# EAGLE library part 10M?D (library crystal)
Monolithic Crystal Filters Source: www.vanlong.com
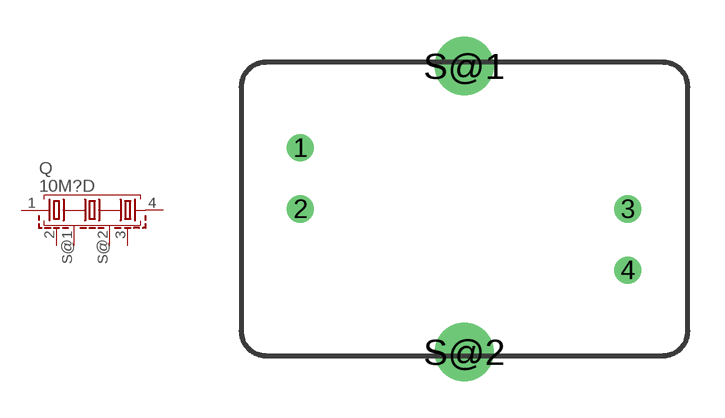
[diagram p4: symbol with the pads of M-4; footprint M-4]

Designator prefix Q

## 10M15D (OC_FARNELL: unknown; OC_NEWARK: unknown), 10M15D1 (OC_FARNELL: unknown; OC_NEWARK: unknown)  [M-4]
1  1  pas
2  2  pas
3  3  pas
4  4  pas
S@1  S  pas
S@2  S  pas

## Footprint M-4 (pad centres in mm)
Monolithic Crystal Filters Source: www.vanlong.com
drill 0.6 pad 1.016 round: 1 -6.7,2.5; 2 -6.7,0; 3 6.7,0; 4 6.7,-2.5
drill 1.6 pad 1.93 round: S@1 0,5.85; S@2 0,-5.85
